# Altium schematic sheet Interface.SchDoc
size A4
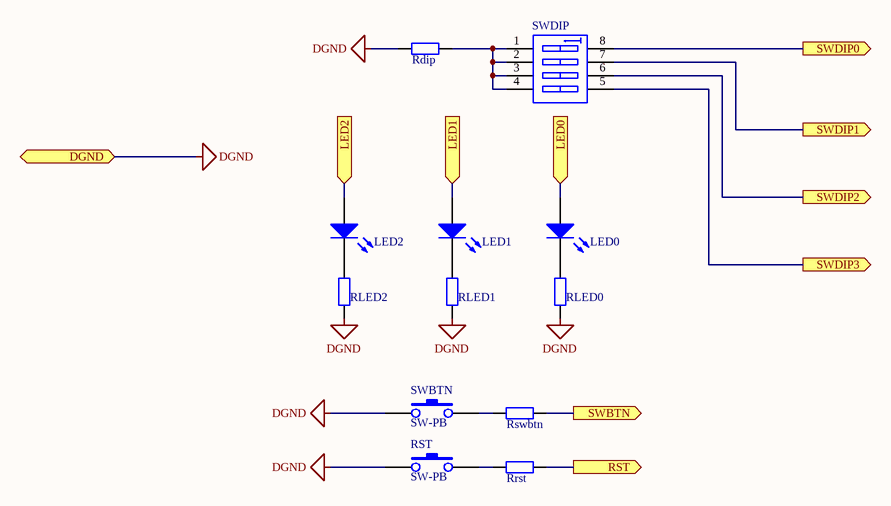
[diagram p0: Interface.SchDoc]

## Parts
LED0  LTST-C170KGKT  [ECE-LED2012-0805SM]  (value not drawn)
LED1  LTST-C170KAKT  [ECE-LED2012-0805SM]  (value not drawn)
LED2  LTST-C170KAKT  [ECE-LED2012-0805SM]  (value not drawn)
Rdip  1K  [ECE-RESC2012-0805SM]  (value not drawn)
RLED0  270R  [ECE-RESC1608-0603SM]  (value not drawn)
RLED1  270R  [ECE-RESC1608-0603SM]  (value not drawn)
RLED2  270R  [ECE-RESC1608-0603SM]  (value not drawn)
Rrst  1K  [ECE-RESC1608-0603SM]  (value not drawn)
RST  SW-PB  [SW-PB]
Rswbtn  1K  [ECE-RESC1608-0603SM]  (value not drawn)
SWBTN  SW-PB  [SW-PB]
SWDIP  *  [ECE-DIP8]  (value not drawn)

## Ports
DGND (bidir), LED0 (in), LED1 (in), LED2 (in), RST (out), SWBTN (out), SWDIP0 (out), SWDIP1 (out), SWDIP2 (out), SWDIP3 (out)

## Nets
DGND: Rdip.1 RLED0.1 RLED1.1 RLED2.1 RST.1 SWBTN.1 ; port DGND
LED0: LED0.1(A) ; port LED0
LED1: LED1.1(A) ; port LED1
LED2: LED2.1(A) ; port LED2
RST: Rrst.2 ; port RST
SWBTN: Rswbtn.2 ; port SWBTN
SWDIP0: SWDIP.8(B1) ; port SWDIP0
SWDIP1: SWDIP.7(B2) ; port SWDIP1
SWDIP2: SWDIP.6(B3) ; port SWDIP2
SWDIP3: SWDIP.5(B4) ; port SWDIP3
NetLED0_2: LED0.2(K) RLED0.2
NetLED1_2: LED1.2(K) RLED1.2
NetLED2_2: LED2.2(K) RLED2.2
NetRdip_2: Rdip.2 SWDIP.1(A1) SWDIP.2(A2) SWDIP.3(A3) SWDIP.4(A4)
NetRrst_1: Rrst.1 RST.2
NetRswbtn_1: Rswbtn.1 SWBTN.2

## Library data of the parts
LED0 = DIO000104: LED GREEN CLEAR 0805 SM; Manufactuer: Lite-On Inc; Assembly Method: Surface Mount; Voltage/Current: 20mA; Item Type: Item; Path: ece/ts/Lists/Stock Inventory
LED1 LED2 = DIO000105: LED RED ORANGE CLEAR 0805 SMD; Manufactuer: Lite-On Inc; Assembly Method: Surface Mount; Voltage/Current: 20mA; Item Type: Item; Path: ece/ts/Lists/Stock Inventory
Rdip = RES000538: RES CER 1K 2012 SM; Manufactuer: Yageo; Manufacturer-PN: RC0805FR-071KL; Assembly Method: Surface Mount; Voltage/Current: 1/8W; Item Type: Item; Path: ece/ts/Lists/Stock Inventory
RLED0-RLED2 = RES000131: RES CER 270R 1608 SM; Assembly Method: Surface Mount; Voltage/Current: 1/10W; Item Type: Item; Path: ece/ts/Lists/Stock Inventory
Rrst Rswbtn = RES000138: RES CER 1K 1608 SM; Manufactuer: Panasonic; Manufacturer-PN: ERJ-3EKF1001V; Assembly Method: Surface Mount; Voltage/Current: 1/10W; Item Type: Item; Path: ece/ts/Lists/Stock Inventory
RST SWBTN = SW-PB: Push Button Switch
SWDIP = Switch-DIP8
